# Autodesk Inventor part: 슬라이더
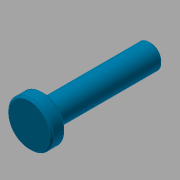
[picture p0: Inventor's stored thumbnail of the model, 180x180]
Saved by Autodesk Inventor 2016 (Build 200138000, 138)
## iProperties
Created: 2019-01
Part Number: 슬라이더
Material: 강철, 연강
Document SubType Name: Modeling
Designer: mduedu
Density: 7.86 g/cm^3
Appearance: 하늘색 중간
Mass: 105.846 g
Surface Area: 45.0711 cm^2
Volume: 13.4664 cm^3
Author: mduedu
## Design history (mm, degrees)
sketch "스케치1"
  geometry: L1 (0, 0)-(8, 0); L2 (8, 0)-(8, 13); L3 (8, 13)-(0, 13); L4 (0, 13)-(0, 0); L5 (8, 0)-(70, 0); L6 (70, 0)-(70, 7); L7 (70, 7)-(8, 7); L8 (8, 7)-(8, 0)
  constraints: 16 end point, 4 parallel, 2 horizontal, 2 perpendicular
  dimensions: "d0" = 70 distance between parallel lines of L6 L4; "d2" = 8 distance of L2.end L3.end; "d3" = 26 diameter of L3 L1; "d4" = 14 diameter of L7 L5
revolve "회전1" sketch "스케치1" stored, may be unused: angle "d5" = 90 deg
chamfer "모따기1" distance "d6" = 1; stored, may be unused: second distance "d7" = 2, angle "d8" = 45 deg
hole "구멍1" diameter "d14" = 4.134; stored, may be unused: countersink angle "d18" = 60 deg, drill point angle "d20" = 118 deg; dims "d15" = 12, "d16" = 6.3, "d17" = 2, "d19" = 15, "d26" = 10, "d27" = 10
chamfer "모따기4" distance "d24" = 1; stored, may be unused: second distance "d25" = 2, angle "d28" = 30 deg
sketch "스케치2"
  geometry: L1 (70, 2.067)-(70, -2.067) reference; L2 (70, 0)-(68, 0); L3 (68, 0)-(68, 2.067); L4 (70, 3.222)-(70, 0); L5 (70, 3.222)-(68, 2.067); L6 (55, 2.067)-(70, 2.067) reference; 1 further point
  constraints: 8 end point, 1 horizontal, 1 midpoint, 1 parallel, 1 perpendicular, 1 point on line
  dimensions: "d29" = 2 horizontal distance of L4.start L3.end; "d31" = 30 deg angle of L2 L5
revolve "회전2" sketch "스케치2" stored, may be unused: angle "d33" = 90 deg
node "솔리드1"
